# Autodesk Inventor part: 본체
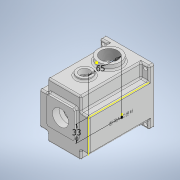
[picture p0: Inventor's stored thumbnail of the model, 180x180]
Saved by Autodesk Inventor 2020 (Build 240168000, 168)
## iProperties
Created: 2022-01
Part Number: 본체
Material: 일반
Document SubType Name: Modeling
Designer: user
Density: 1 g/cm^3
Appearance: 기본값
Author: user
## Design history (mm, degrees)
sketch "스케치21"
  geometry: 1 further point
sketch "스케치30"
  geometry: L1 (49, -55)-(-49, -55); L2 (-49, -55)-(-49, 55); L3 (-49, 55)-(49, 55); L4 (49, 55)-(49, -55); L5 (49, -55)-(-49, 55); L6 (-49, -55)-(49, 55); 1 further point
  constraints: 12 end point, 2 midpoint, 2 parallel, 1 horizontal, 1 perpendicular
  dimensions: "d101" = 98 distance of L2.end L3.end; "d102" = 110 distance of L1.end L2.end
extrude "돌출16" new body sketch "스케치30" stored distance "d103" = 130; taper "d104" = 0 deg
sketch "스케치31" dims "d106" = 84
  geometry: L1 (49, -55)-(-49, -55) reference; L2 (0, -55)-(0, -5); L3 (0, -5)-(0, 45); L4 (0, 45)-(-23, 45); L5 (-23, 45)-(23, 45); L6 (23, 45)-(23, 30.143); L7 (23, 30.143)-(-23, 30.143); L8 (-23, 30.143)-(-23, 45); L9 (26, 27.143)-(26, 48); L10 (26, 48)-(-26, 48); L11 (-26, 48)-(-26, 27.143); L12 (-26, 27.143)-(26, 27.143); C1 r 45 at (0, -5); 3 further points
  constraints: 22 end point, 4 parallel, 3 perpendicular, 2 vertical, 1 centre point, 1 coincident, 1 horizontal, 1 midpoint, 6 other
  dimensions: "d105" = 50 distance of L2.start L2.end; "d107" = 50 distance of L3.start L3.end; "d108" = 23 distance of L3.end L4.end; "d109" = 46 distance of L6.end L7.end; "d110" = 3 distance between parallel lines of L6 L9; "d111" = 3 dimension on C1
extrude "돌출17" cut sketch "스케치31" distance "d112" = 9; taper "d113" = 0 deg
sketch "스케치32" dims "d115" = 84
  geometry: L1 (-49, -55)-(49, -55) reference; L2 (0, -55)-(0, -5); L3 (0, -5)-(0, 45); L4 (0, 45)-(-23, 45); L5 (-23, 45)-(23, 45); L6 (23, 45)-(23, 30.143); L7 (23, 30.143)-(-23, 30.143); L8 (-23, 30.143)-(-23, 45); 3 further points
  constraints: 14 end point, 2 parallel, 2 perpendicular, 2 vertical, 1 coincident, 1 horizontal, 1 midpoint, 3 other
  dimensions: "d114" = 50 distance of L2.start L2.end; "d116" = 50 distance of L3.start L3.end; "d117" = 23 distance of L3.end L4.end; "d118" = 46 distance of L6.end L7.end
extrude "돌출18" cut sketch "스케치32" distance "d119" = 112; taper "d120" = 0 deg
sketch "스케치33"
  geometry: L1 (-49, -55)-(49, -55) reference; L2 (0, -55)-(0, -5); L3 (0, -5)-(0, 6); L4 (0, -5)-(0, -25); C1 r 21 at (0, 6); C2 r 15 at (0, -25); 3 further points
  constraints: 6 end point, 2 centre point, 2 coincident, 2 point on line, 1 midpoint, 1 vertical
  dimensions: "d121" = 50 distance of L2.start L2.end; "d122" = 11 distance of L2.end L3.end; "d123" = 20 distance of L2.end L4.end; "d124" = 42 diameter of C1; "d125" = 30 diameter of C2
extrude "돌출19" join sketch "스케치33" distance "d126" = 7; taper "d127" = 0 deg
sketch "스케치34"
  geometry: L1 (-49, 55)-(-49, -55) reference; L2 (-49, 55)-(-33, 55); L3 (-33, 55)-(-33, 28); L4 (-33, 28)-(-49, 28); L5 (-49, 28)-(-49, 55); L6 (-49, -55)-(49, -55) reference; L7 (-49, -55)-(-33, -55); L8 (-33, -55)-(-33, -38); L9 (-33, -38)-(-49, -38); L10 (-49, -38)-(-49, -55); L11 (49, -55)-(33, -55); L12 (33, -55)-(33, -38); L13 (33, -38)-(49, -38); L14 (49, -38)-(49, -55); L15 (49, 55)-(-49, 55) reference; L16 (49, 55)-(33, 55); L17 (33, 55)-(33, 28); L18 (33, 28)-(49, 28); L19 (49, 28)-(49, 55); 6 further points
  constraints: 32 end point, 8 parallel, 4 horizontal, 4 perpendicular
  dimensions: "d128" = 16 distance of L3.end L4.end; "d129" = 27 distance of L2.end L3.end; "d130" = 16 distance of L9.end L8.end; "d131" = 17 distance of L8.end L7.end; "d132" = 16 distance of L12.end L13.end; "d133" = 17 distance of L11.end L12.end; "d134" = 16 distance of L18.end L17.end; "d135" = 27 distance of L17.end L16.end
extrude "돌출20" cut sketch "스케치34" distance "d136" = 120; taper "d137" = 0 deg
sketch "스케치35"
  geometry: L1 (98, 0)-(0, 0) reference; L2 (49, 0)-(49, -40); L3 (49, -40)-(49, -89); C1 r 15 at (49, -89); C2 r 22.5 at (49, -40); 1 further point
  constraints: 4 end point, 2 centre point, 2 coincident, 1 midpoint, 1 point on line, 1 vertical
  dimensions: "d138" = 40 distance of L2.start L2.end; "d139" = 49 distance of L2.end L3.end; "d140" = 30 diameter of C1; "d141" = 45 diameter of C2
extrude "돌출21" join sketch "스케치35" distance "d142" = 5; taper "d143" = 0 deg
extrude "돌출22" join sketch "스케치35" distance "d144" = 10; taper "d145" = 0 deg
sketch "스케치36"
  geometry: C1 r 15 at (0, 0) reference; C2 r 10 at (0, 0); 1 further point
  constraints: 1 centre point, 1 coincident
  dimensions: "d146" = 20 diameter of C2
extrude "돌출23" cut sketch "스케치36" distance "d147" = 20; taper "d148" = 0 deg
sketch "스케치37"
  geometry: C1 r 10 at (23, 80) reference; C2 r 15 at (23, 80); 1 further point
  constraints: 1 centre point, 1 coincident
  dimensions: "d149" = 30 diameter of C2
extrude "돌출24" cut sketch "스케치37" distance "d150" = 5; taper "d151" = 0 deg
sketch "스케치38"
  geometry: 1 further point
sketch "스케치39"
  geometry: C1 r 22.5 at (0, 0) reference; 2 further points
  constraints: 1 coincident
hole "구멍4" sketch "스케치39" at (0, 0) diameter "d152" = 33.376; stored, may be unused: countersink angle "d156" = 90 deg, drill point angle "d158" = 118 deg; dims "d153" = 70, "d154" = 4, "d155" = 2, "d157" = 77.3
sketch "스케치40" dims "d162" = 8
  geometry: L1 (-49, -55)-(49, -55) reference; L2 (0, -55)-(0, -5); L3 (36, -1)-(41.644, -1); L4 (4, -9)-(-4, -9); L5 (-4, -9)-(-4, -1); L6 (-4, -1)-(4, -1); L7 (4, -1)-(4, -9); L8 (4, -9)-(-4, -1); L9 (-4, -9)-(4, -1); L10 (-4, -1)-(-47.386, -1); L11 (-4, -9)-(-49, -9); L12 (-49, -38)-(-49, 28) reference; L13 (4, -9)-(44.822, -9); L14 (4, -1)-(44.822, -1); C1 r 4 at (-36, -5); C2 r 42 at (0, -5); A1 r 36 centre (0, -5) between (-36, -5) and (36, -5); A2 r 45 centre (0, -5) between (-26, 31.729) and (26, 31.729) reference; A3 r 42 centre (0, -5) between (-23, 30.143) and (23, 30.143) reference; 7 further points
  constraints: 24 end point, 5 horizontal, 4 point on circle, 3 centre point, 3 midpoint, 3 point on line, 2 coincident, 2 horizontal alignment, 2 parallel, 1 concentric, 1 perpendicular, 1 vertical, 3 other
  dimensions: "d159" = 50 distance of L2.start L2.end; "d160" = 72 diameter of A1; "d161" = 8 diameter of C1; "d163" = 8 distance of L5.end L6.end; "d164" = 8 distance of L4.end L5.end
extrude "돌출25" join sketch "스케치40" distance "d165" = 121; taper "d166" = 0 deg
sketch "스케치41"
  geometry: L1 (42, -48)-(-42, -48); L2 (-42, -48)-(-42, 48); L3 (-42, 48)-(42, 48); L4 (42, 48)-(42, -48); L5 (42, -48)-(-42, 48); L6 (-42, -48)-(42, 48); 1 further point
  constraints: 12 end point, 2 midpoint, 2 parallel, 1 horizontal, 1 perpendicular
  dimensions: "d167" = 84 distance of L2.end L3.end; "d168" = 96 distance of L1.end L2.end
hole "구멍5" sketch "스케치41" at (-42, 48), (-42, -48), (42, -48), (42, 48) diameter "d169" = 7; stored, may be unused: countersink angle "d173" = 90 deg, drill point angle "d175" = 118 deg; dims "d170" = 70, "d171" = 4, "d172" = 2, "d174" = 77.3
sketch "스케치42"
  geometry: A1 r 4 centre (-36, -5) between (-36, -9) and (-36, -1) reference; A2 r 4 centre (36, -5) between (36, -1) and (36, -9) reference; 3 further points
  constraints: 2 coincident
hole "구멍6" sketch "스케치42" at (-36, -5), (36, -5) diameter "d176" = 3.242; stored, may be unused: countersink angle "d180" = 90 deg, drill point angle "d182" = 118 deg; dims "d177" = 7, "d178" = 4, "d179" = 2, "d181" = 9
sketch "스케치46"
  geometry: A1 r 21 centre (0, 6) between (8.978, -12.984) and (-8.978, -12.984) reference; 2 further points
  constraints: 1 coincident
hole "구멍7" sketch "스케치46" at (0, 6) diameter "d188" = 28; stored, may be unused: countersink angle "d192" = 90 deg, drill point angle "d194" = 118 deg; dims "d189" = 7, "d190" = 35, "d191" = 10, "d193" = 9
sketch "스케치47"
  geometry: A1 r 15 centre (0, -25) between (-8.978, -12.984) and (8.978, -12.984) reference; 2 further points
  constraints: 1 coincident
hole "구멍8" sketch "스케치47" at (0, -25) diameter "d195" = 19; stored, may be unused: countersink angle "d199" = 90 deg, drill point angle "d201" = 0 deg; dims "d196" = 7, "d197" = 22, "d198" = 7, "d200" = 10
sketch "스케치48"
  geometry: C1 r 14 at (0, 6) reference; C2 r 16 at (0, 6); 1 further point
  constraints: 1 centre point, 1 coincident
  dimensions: "d202" = 32 diameter of C2
extrude "돌출26" cut sketch "스케치48" distance "d203" = 8.3; taper "d204" = 0 deg
sketch "스케치49"
  geometry: L1 (-27, -21)-(27, -21); L2 (27, -21)-(27, 33); L3 (27, 33)-(-27, 33); L4 (-27, 33)-(-27, -21); L5 (-27, -21)-(27, 33); L6 (27, -21)-(-27, 33); C1 r 16 at (0, 6) reference; 1 further point
  constraints: 12 end point, 2 midpoint, 2 parallel, 1 horizontal, 1 perpendicular
  dimensions: "d205" = 54 distance of L3.end L2.end; "d206" = 54 distance of L2.end L1.end
extrude "돌출27" join sketch "스케치49" distance "d207" = 7; taper "d208" = 0 deg
sketch "스케치50"
  geometry: 1 further point
sketch "스케치51"
  geometry: 1 further point
sketch "스케치52" dims "d105" = 50, "d106" = 84, "d107" = 50, "d108" = 23, "d109" = 46, "d110" = 3, "d111" = 3
  geometry: L1 (-130, 17)-(-130, 83) reference; L2 (-10, 83)-(-130, 83) reference; 2 further points
  constraints: 1 other
  dimensions: "d209" = 65 distance from line of L1 point (-65, 50); "d210" = 33 distance from line of L2 point (-65, 50)
fillet "모깎기2" dims "d215" = 3
fillet "모깎기3" dims "d216" = 3
fillet "모깎기4" dims "d217" = 3
fillet "모깎기5" dims "d218" = 3
fillet "모깎기6" dims "d219" = 3
sketch "스케치53"
  geometry: 1 further point
fillet "모깎기7" dims "d223" = 3
sketch "스케치54"
  geometry: 1 further point
fillet "모깎기8" dims "d224" = 3
sketch "스케치55"
  geometry: 1 further point
fillet "모깎기9" dims "d225" = 3
fillet "모깎기10" dims "d226" = 0.3
chamfer "모따기3" distance "d227" = 1; stored, may be unused: second distance "d228" = 2, angle "d229" = 45 deg
fillet "모깎기11" dims "d230" = 6
fillet "모깎기12" dims "d231" = 3
chamfer "모따기4" distance "d232" = 1; stored, may be unused: second distance "d233" = 2, angle "d234" = 45 deg
node "솔리드2"
feature "A9D066F2-1C7D-4E18-AEED-F7BC21143FA4" dims "d169" = 7, "d170" = 70, "d171" = 4, "d172" = 2, "d173" = 90 deg, "d174" = 77.3, "d175" = 118 deg
